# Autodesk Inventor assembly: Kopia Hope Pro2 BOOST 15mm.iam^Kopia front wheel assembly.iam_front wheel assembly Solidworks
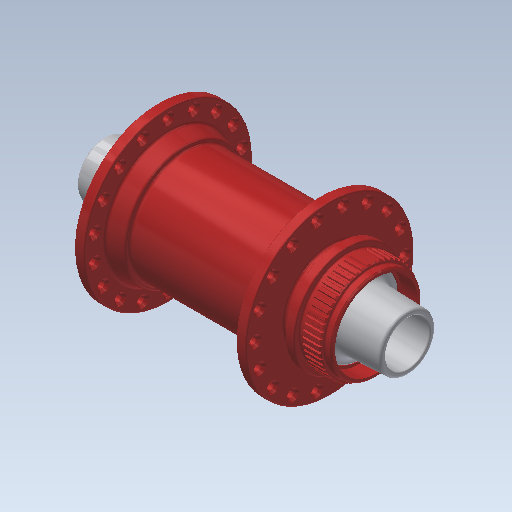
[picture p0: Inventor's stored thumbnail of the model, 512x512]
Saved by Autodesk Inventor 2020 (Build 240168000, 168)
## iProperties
Created: 2017-09
Part Number: Kopia Hope Pro2 BOOST 15mm.iam^Kopia front wheel assembly.iam_front wheel assembly Solidworks
Material: Ogólny
Document SubType Name: Assembly
Designer: Tomasz
Sending System: SolidWorks 2017
Last Author: Tomasz
Last Saved: 2017-09-11
Author: Tomasz
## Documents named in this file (5)
- C:\Users\bruno\Documents\1-Cours-2020-21\1STI2D-2020-21\IT\6. Antivol\Inventor-Antivol\INVENTOR 2018_Steel Hardtail B+\Kopia Hope Pro2 BOOST 15mm.iam^Kopia front wheel assembly.iam_front wheel assembly Solidworks.iam
- C:\Users\bruno\Documents\1-Cours-2020-21\1STI2D-2020-21\IT\6. Antivol\Inventor-Antivol\INVENTOR 2018_Steel Hardtail B+\Kopia hub body.ipt^Kopia Hope Pro2 BOOST 15mm.iam_Kopia front wheel assembly.iam_front wheel assembly.ipt
- C:\Users\bruno\Documents\1-Cours-2020-21\1STI2D-2020-21\IT\6. Antivol\Inventor-Antivol\INVENTOR 2018_Steel Hardtail B+\Kopia right spacer.ipt^Kopia Hope Pro2 BOOST 15mm.iam_Kopia front wheel assembly.iam_front wheel assembly.ipt
- C:\Users\bruno\Documents\1-Cours-2020-21\1STI2D-2020-21\IT\6. Antivol\Inventor-Antivol\INVENTOR 2018_Steel Hardtail B+\Kopia roulement_61902-2rs1_2.iam^Kopia Hope Pro2 BOOST 15mm.iam_Kopia front wheel assembly.iam_front wheel assembly.iam
- C:\Users\bruno\Documents\1-Cours-2020-21\1STI2D-2020-21\IT\6. Antivol\Inventor-Antivol\INVENTOR 2018_Steel Hardtail B+\Kopia left spacer.ipt^Kopia Hope Pro2 BOOST 15mm.iam_Kopia front wheel assembly.iam_front wheel assembly.ipt
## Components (5 placed, 4 different names)
1. Kopia hub body.ipt^Kopia Hope Pro2 BOOST 15mm.iam_Kopia front wheel assembly.iam_front wheel assembly Solidworks:1
2. Kopia right spacer.ipt^Kopia Hope Pro2 BOOST 15mm.iam_Kopia front wheel assembly.iam_front wheel assembly Solidworks:1
3. Kopia roulement_61902-2rs1_2.iam^Kopia Hope Pro2 BOOST 15mm.iam_Kopia front wheel assembly.iam_front wheel assembly Solidworks:1 [sub-assembly]
4. Kopia roulement_61902-2rs1_2.iam^Kopia Hope Pro2 BOOST 15mm.iam_Kopia front wheel assembly.iam_front wheel assembly Solidworks:2 [sub-assembly]
5. Kopia left spacer.ipt^Kopia Hope Pro2 BOOST 15mm.iam_Kopia front wheel assembly.iam_front wheel assembly Solidworks:1
